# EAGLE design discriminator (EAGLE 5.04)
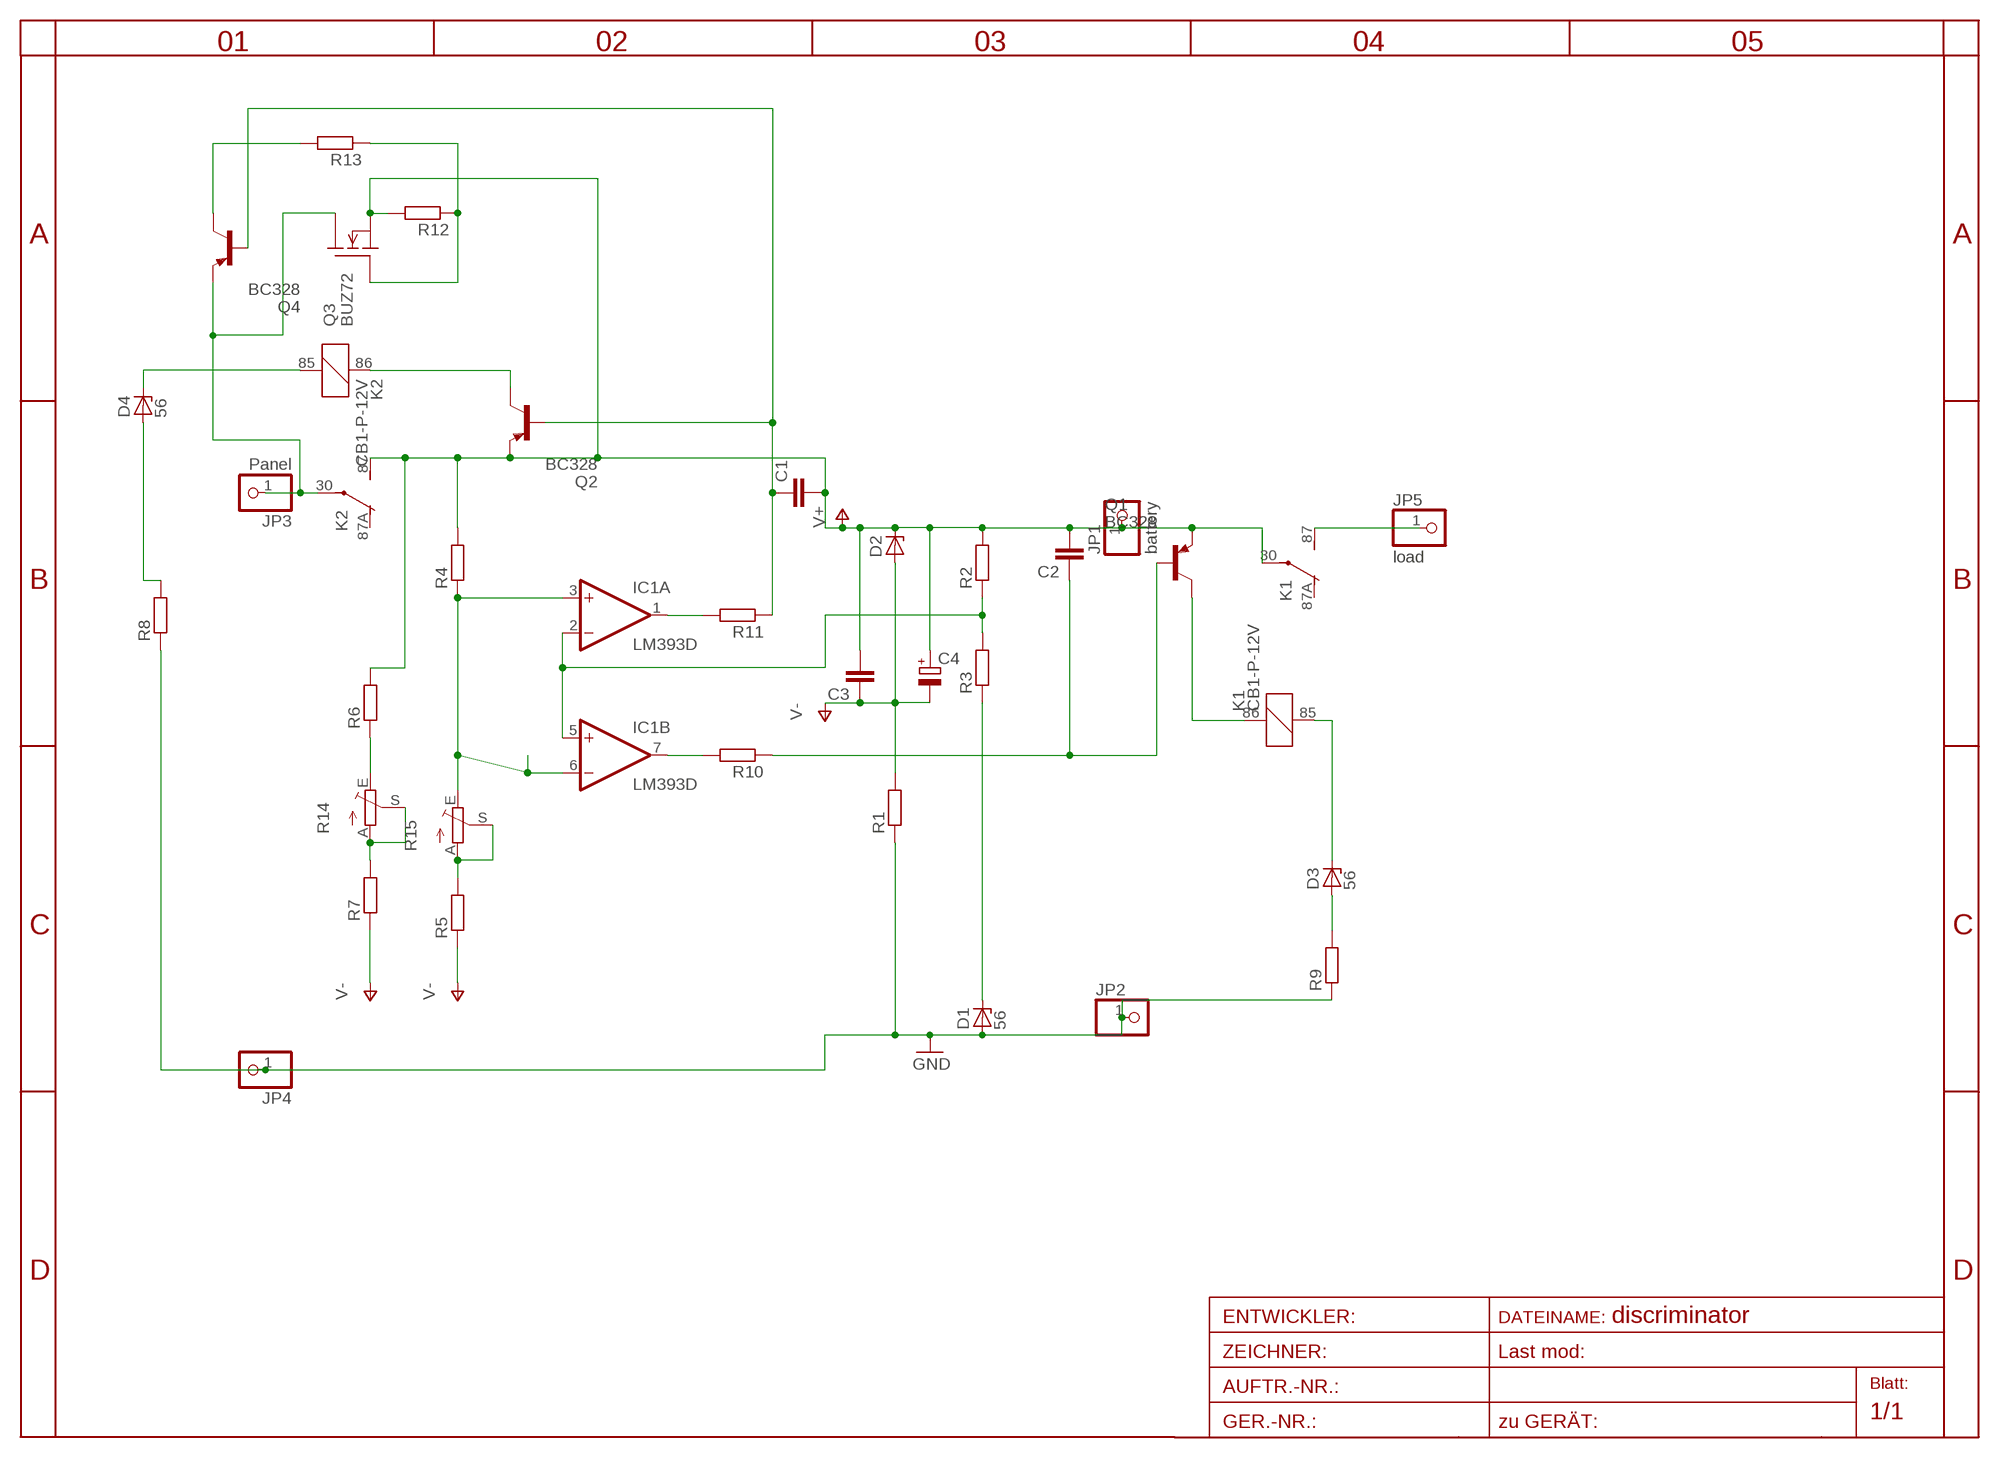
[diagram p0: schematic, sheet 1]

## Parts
C1  C-EU025-025X050  [C025-025X050]
C2  C-EU025-025X050  [C025-025X050]
C3  C-EU025-025X050  [C025-025X050]
C4  CPOL-EU5-13  [2,5-5-FLAT]
D1  56  ZENER-DIODEDO35Z10  [DO35Z10]
D2  ZENER-DIODEDO35Z10  [DO35Z10]
D3  56  ZENER-DIODEDO35Z10  [DO35Z10]
D4  56  ZENER-DIODEDO35Z10  [DO35Z10]
IC1  LM393D  [SO08]
JP1  battery  PINHD-1X1  [1X01]
JP2  PINHD-1X1  [1X01]
JP3  Panel  PINHD-1X1  [1X01]
JP4  PINHD-1X1  [1X01]
JP5  load  PINHD-1X1  [1X01]
K1  CB1-P-12V  [CB1]
K2  CB1-P-12V  [CB1]
Q1  BC328  [TO92-EBC]
Q2  BC328  [TO92-EBC]
Q3  BUZ72  [TO220]
Q4  BC328  [TO92-EBC]
R1  R-EU_0204/7  [0204/7]
R2  R-EU_0204/7  [0204/7]
R3  R-EU_0204/7  [0204/7]
R4  R-EU_0204/7  [0204/7]
R5  R-EU_0204/7  [0204/7]
R6  R-EU_0204/7  [0204/7]
R7  R-EU_0204/7  [0204/7]
R8  R-EU_0204/7  [0204/7]
R9  R-EU_0204/7  [0204/7]
R10  R-EU_0204/7  [0204/7]
R11  R-EU_0204/7  [0204/7]
R12  R-EU_0204/7  [0204/7]
R13  R-EU_0204/7  [0204/7]
R14  TRIM_EU-CA6V  [CA6V]
R15  TRIM_EU-CA6V  [CA6V]

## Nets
GND: D1.A JP2.1 JP4.1 R1.1 R8.1 R9.1
LOAD: JP5.1 K1.87(2:S)
N$1: D1.C R3.1
N$2: R6.1 R14.E
N$3: R7.2 R14.A R14.S
N$4: IC1.2(A:-IN) IC1.5(B:+IN) R2.1 R3.2
N$5: K1.86 Q1.C
N$6: D3.C K1.85
N$7: D3.A R9.2
N$8: K2.86 Q2.C
N$9: D4.C K2.85
N$10: D4.A R8.2
N$11: R5.2 R15.A R15.S
N$12: IC1.3(A:+IN) IC1.6(B:-IN) R4.1 R15.E
N$14: IC1.1(A:OUT) R11.2
N$15: IC1.7(B:OUT) R10.2
N$16: C1.1 Q2.B Q4.B R11.1
N$17: C2.1 Q1.B R10.1
N$19: Q3.1(G) R12.1 R13.1
N$20: Q4.C R13.2
PANEL: JP3.1 K2.30(2:P) Q3.2(D) Q4.E
V+: C1.2 C2.2 C3.2 C4.+ D2.C JP1.1 K1.30(2:P) K2.87(2:S) Q1.E Q2.E Q3.3(S) R2.2 R4.2 R6.2 R12.2
V-: C3.1 C4.- D2.A R1.2 R5.1 R7.1
Unconnected: K1.87A(2:O) K2.87A(2:O)

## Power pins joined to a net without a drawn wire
V+: IC1.8(P:V+)
V-: IC1.4(P:V-)

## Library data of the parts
C1-C3 = rcl-2:C-EU: CAPACITOR, European symbol
C4 = rcl-2:CPOL-EU: POLARIZED CAPACITOR, European symbol
D1-D4 = diode-1:ZENER-DIODE: Z-Diode
IC1 = linear:LM393: COMPARATOR
JP1-JP5 = pinhead:PINHD-1X1: PIN HEADER
K1 K2 = relay:CB1*: HIGH POWER AUTOMOTIVE RELAY Form C NAiS Source: http://www.mew-europe.com/.. en_ds_61202_0000.pdf
Q1 Q2 Q4 = transistor-pnp:BC328*: PNP Transistror
Q3 = transistor-fet:BUZ72: N-Channel Enhancement MOSFET 100V; 10A; 0,2Ohm
R1-R13 = rcl-2:R-EU_: RESISTOR, European symbol
R14 R15 = pot:TRIM_EU-: POTENTIOMETER

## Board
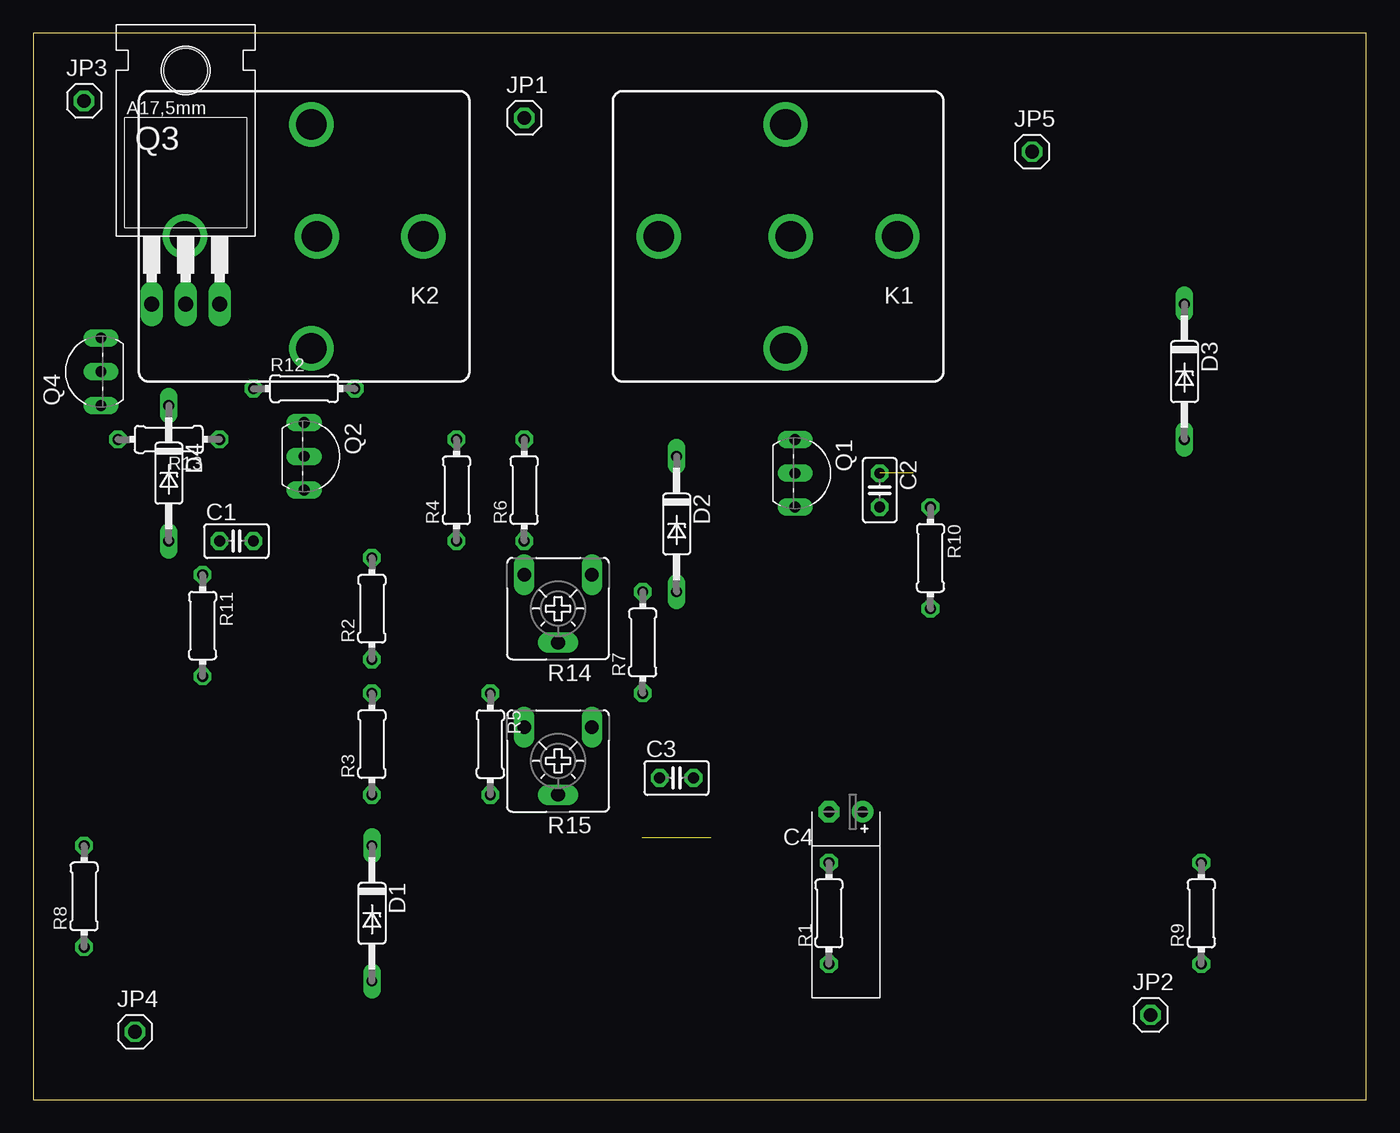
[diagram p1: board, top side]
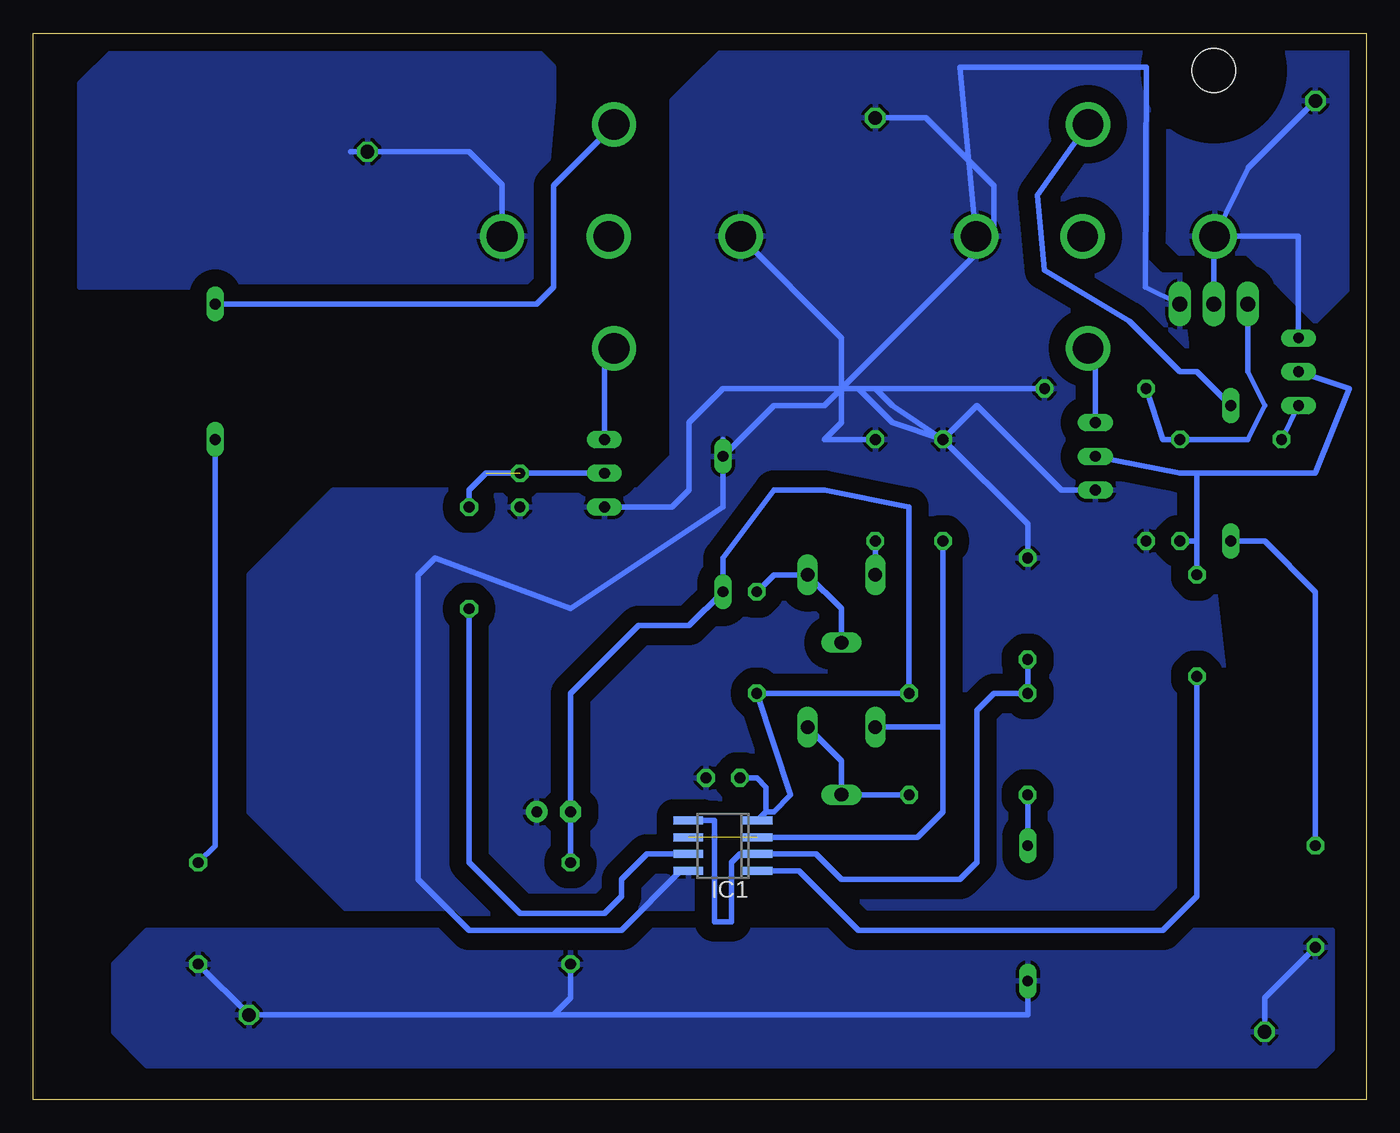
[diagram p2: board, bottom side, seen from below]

Size 100 x 80 mm. Coordinates in mm from the lower left corner, seen from the top.
Outline: 0,0 100,0 100,80 0,80 0,0
Copper layers (1*16): Top 0.035mm / dielectric 1.5mm / Bottom 0.035mm
Design rules "default": minimum track width 10mil, minimum drill 24mil, track to track 8mil, track to pad 8mil, pad to pad 8mil, via to via 8mil, smd to smd 8mil, copper to edge 40mil, drill to drill 8mil, minimum pad ring 10mil, minimum via ring 8mil, stop-mask expansion 4mil, vias tented up to drill 0mil, thermal gap 10mil

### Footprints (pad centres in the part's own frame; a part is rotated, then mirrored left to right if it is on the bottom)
C025-025X050 = drill 0.813 octagon: 1 -1.27,0; 2 1.27,0
2,5-5-FLAT = drill 0.813 pad 1.6 round: + -1.27,0 | drill 0.813 pad 1.6 octagon: - 1.27,0
DO35Z10 = drill 0.813 long: A 5.08,0; C -5.08,0
SO08 = smd 0.6 x 2.2: 1 -1.905,-2.6; 2 -0.635,-2.6; 3 0.635,-2.6; 4 1.905,-2.6; 5 1.905,2.6; 6 0.635,2.6; 7 -0.635,2.6; 8 -1.905,2.6
1X01 = drill 1.016 octagon: 1 0,0
CB1 = drill 2.3 round: 30 8.95,0; 85 -0.55,-8.4; 86 -0.55,8.4; 87 -8.95,0; 87A -0.95,0
TO92-EBC = drill 0.813 long: B 0,-1.27; C -2.54,-1.27; E 2.54,-1.27
TO220 = drill 1.118 long: 1 -2.54,-6.35; 2 0,-6.35; 3 2.54,-6.35 | hole 3.302: 0,11.176
0204/7 = drill 0.813 octagon: 1 -3.81,0; 2 3.81,0
CA6V = drill 1.016 long: A -2.54,-2.54; E 2.54,-2.54; S 0,2.54

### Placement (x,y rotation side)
C1  15.24,41.91 0 top
C2  63.5,45.72 270 top
C3  48.26,24.13 0 top
C4  60.96,21.59 180 top
D1  25.4,13.97 270 top
D2  48.26,43.18 270 top
D3  86.36,54.61 270 top
D4  10.16,46.99 270 top
IC1  48.26,19.05 90 bottom
JP1  36.83,73.66 0 top
JP2  83.82,6.35 0 top
JP3  3.81,74.93 0 top
JP4  7.62,5.08 0 top
JP5  74.93,71.12 0 top
K1  55.88,64.77 180 top
K2  20.32,64.77 180 top
Q1  58.42,46.99 270 top
Q2  21.59,48.26 270 top
Q3  11.43,66.04 0 top
Q4  3.81,54.61 90 top
R1  59.69,13.97 90 top
R2  25.4,36.83 90 top
R3  25.4,26.67 90 top
R4  31.75,45.72 90 top
R5  34.29,26.67 270 top
R6  36.83,45.72 90 top
R7  45.72,34.29 90 top
R8  3.81,15.24 90 top
R9  87.63,13.97 90 top
R10  67.31,40.64 270 top
R11  12.7,35.56 270 top
R12  20.32,53.34 0 top
R13  10.16,49.53 180 top
R14  39.37,36.83 180 top
R15  39.37,25.4 180 top

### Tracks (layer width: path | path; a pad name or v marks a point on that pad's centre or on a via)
GND
  Bottom 0.406: R9.1 JP2.1 62.23,6.35 | 62.23,6.35 60.96,6.35 59.69,7.62 R1.1 | D1.A 25.4,6.35 62.23,6.35 | JP4.1 7.62,7.62 R8.1
  pour Bottom (isolate 1.27, rank 4): 2.54,12.7 91.44,12.7 93.98,10.16 93.98,5.08 91.44,2.54 3.81,2.54 2.54,3.81
LOAD
  Bottom 0.406: K1.87 64.83,68.64 67.31,71.12 JP5.1 76.2,71.12
  pour Bottom (isolate 1.27, rank 4): 60.96,74.93 60.96,77.47 62.23,78.74 93.98,78.74 96.52,76.2 96.52,60.96 62.23,60.96
N$1
  Bottom 0.406: D1.C R3.1
N$2
  Bottom 0.406: R6.1 R14.E
N$3
  Bottom 0.406: R14.S 39.37,36.83 R14.A 44.45,39.37 R7.2
N$4
  Bottom 0.406: IC1.5 48.9,20.95 48.9,13.34 47.62,13.34 47.62,17.78 46.99,18.41 IC1.2 41.27,18.41 39.37,16.51 30.48,16.51 29.21,17.78 29.21,29.21 27.94,30.48 R3.2 R2.1
N$5
  Bottom 0.406: Q1.C 57.15,55.65 K1.86
N$6
  Bottom 0.406: K1.85 56.43,73.11 60.96,68.58 60.96,60.96 62.23,59.69 D3.C
N$7
  Bottom 0.406: D3.A 86.36,19.05 R9.2
N$8
  Bottom 0.406: Q2.C 20.32,55.65 K2.86
N$9
  Bottom 0.406: K2.85 24.68,67.86 24.13,62.23 17.78,58.42 13.97,54.61 12.7,54.61 D4.C
N$10
  Bottom 0.406: R8.2 3.81,38.1 7.62,41.91 D4.A
N$11
  Bottom 0.406: R5.2 R15.S 39.37,25.4 R15.A
N$12  (1 unrouted)
  Bottom 0.406: 31.75,27.94 31.75,21.59 33.66,19.68 IC1.3 | 31.75,27.94 R4.1 | 31.75,27.94 R15.E
N$14
  Bottom 0.406: IC1.1 42.55,17.14 38.1,12.7 15.24,12.7 12.7,15.24 R11.2
N$15
  Bottom 0.406: IC1.7 53.98,18.41 55.88,16.51 55.88,15.24 57.15,13.97 63.5,13.97 67.31,17.78 R10.2
N$16
  Bottom 0.406: 13.97,46.99 Q2.B | 13.97,46.99 12.7,46.99 12.7,41.91 | 12.7,41.91 R11.1 | 13.97,46.99 3.81,46.99 1.27,53.34 Q4.B | 12.7,41.91 C1.1
N$17  (1 unrouted)
  Bottom 0.406: Q1.B 66.04,46.99 67.31,45.72 R10.1
N$19
  Bottom 0.406: Q3.1 8.89,54.61 7.62,52.07 8.89,49.53 15.24,49.53 | 15.24,49.53 R12.1 | 15.24,49.53 R13.1
N$20
  Bottom 0.406: R13.2 Q4.C
PANEL
  Bottom 0.406: K2.30 8.83,69.91 JP3.1 | K2.30 11.43,64.77 Q3.2 | K2.30 5.08,64.77 Q4.E
  pour Bottom (isolate 1.27): 0,80.01 0,62.23 3.81,58.42 8.89,63.5 12.7,63.5 13.97,63.5 15.24,64.77 15.24,80.01
V+
  Bottom 0.406: IC1.8 51.44,17.14 55.88,12.7 67.31,12.7 71.12,16.51 71.12,39.37 69.85,40.64 59.69,36.83 48.26,44.45 D2.C | D2.C 44.45,52.07 40.64,52.07 39.37,53.34 | 39.37,53.34 39.37,57.15 46.99,64.77 K1.30 | R6.2 40.64,49.53 39.37,50.8 39.37,53.34 | R4.2 35.56,50.8 38.1,53.34 | Q2.E 22.86,45.72 29.21,52.07 R4.2 | R4.2 35.56,52.07 36.83,53.34 38.1,53.34 | 38.1,53.34 39.37,53.34 | R2.2 25.4,43.18 R4.2 | K2.87 27.94,64.77 39.37,53.34 | JP1.1 33.02,73.66 27.94,68.58 27.94,64.83 K2.87 | 39.37,53.34 48.26,53.34 50.8,50.8 50.8,45.72 52.07,44.45 Q1.E | D2.C 48.26,49.53 | Q3.3 16.57,60.96 16.51,77.47 30.48,77.47 K2.87 | 38.1,53.34 R12.2
  pour Bottom (isolate 1.27, rank 5): 13.97,60.96 13.97,77.47 16.51,80.01 46.99,80.01 52.07,74.93 52.07,48.26 54.61,45.72 77.47,45.72 83.82,39.37 83.82,21.59 76.2,13.97 11.43,13.97 8.89,16.51
V-
  Bottom 0.406: R5.1 34.29,44.45 40.64,45.72 44.45,45.72 48.26,40.64 D2.A 50.8,35.56 54.61,35.56 59.69,30.48 C4.- | R5.1 R7.1 | R5.1 R7.1 | R7.1 43.18,22.86 44.45,21.59 45.02,21.59 | 45.02,21.59 IC1.4 | C4.- R1.2 C4.- | 45.02,21.59 45.02,23.43 45.72,24.13 C3.1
